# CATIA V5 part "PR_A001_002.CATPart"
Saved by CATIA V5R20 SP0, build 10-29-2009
Part number: PR_A001_002
Nomenclature: PR_A001_002
Source: Unknown
Description: Profilé 30x30x460
Bounding box of the stored display mesh (mm): x -15 to 15, y -15 to 15, z 0 to 818
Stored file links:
  C:\Users\halimelbaba\Documents\cmv\plan  d\PR_A001_002.CATPart
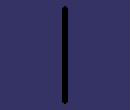
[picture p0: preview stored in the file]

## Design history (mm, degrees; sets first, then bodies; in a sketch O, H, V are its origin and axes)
Body1 "MANIFOLD_SOLID_BREP #6353" (main body)
  Solid1: solid without history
